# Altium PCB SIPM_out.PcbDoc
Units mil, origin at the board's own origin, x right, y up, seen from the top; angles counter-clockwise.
Board outline 1885 x 1885 mil, 2 copper layers (Top Layer, Bottom Layer); 43 components, 15 nets, 149 pads, 10 vias.
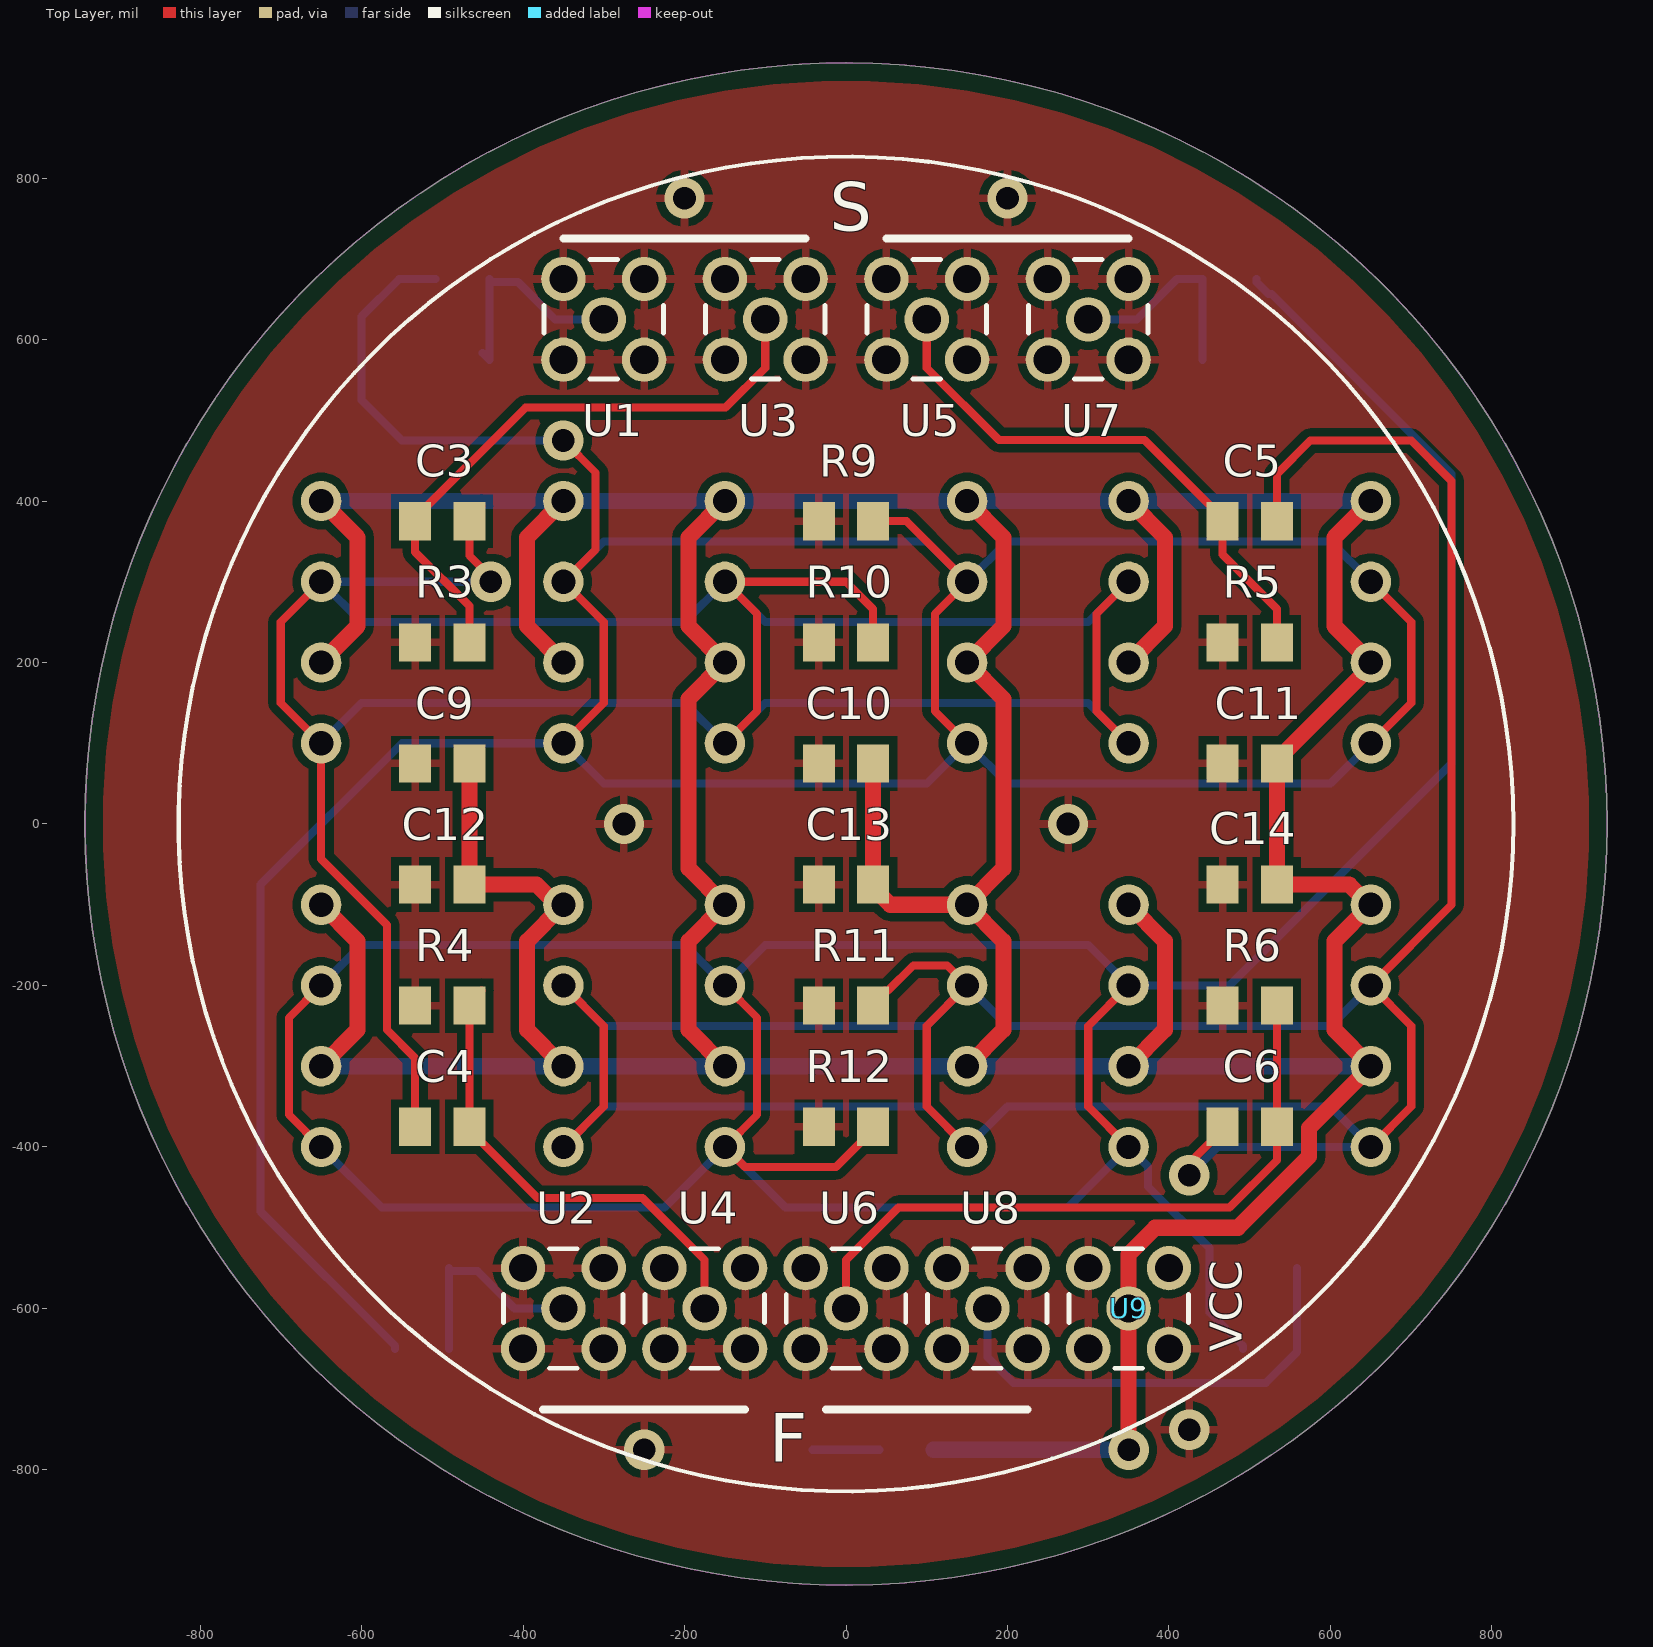
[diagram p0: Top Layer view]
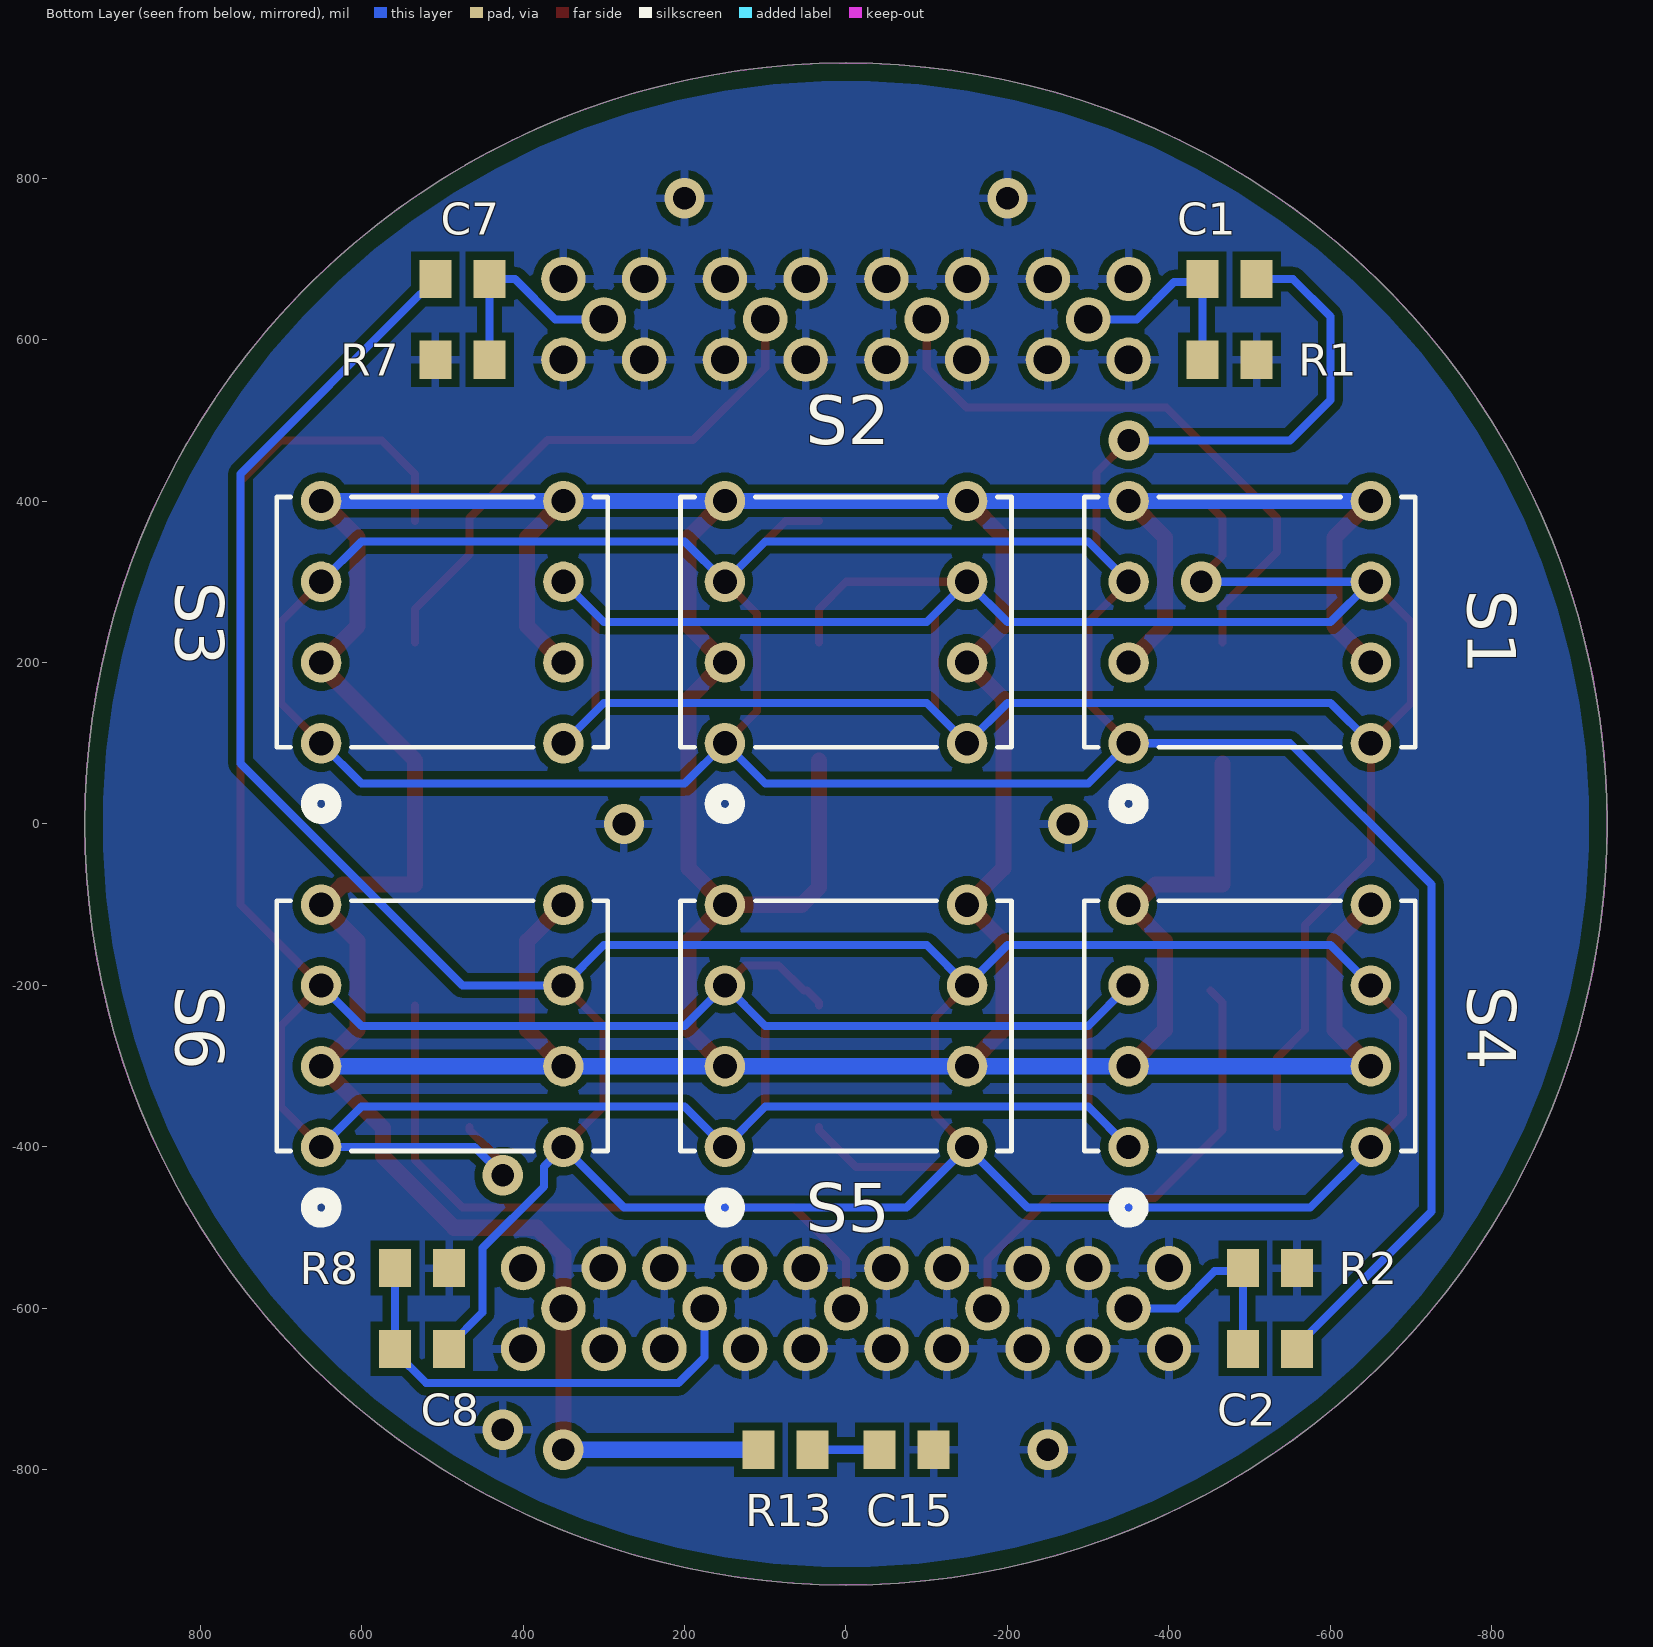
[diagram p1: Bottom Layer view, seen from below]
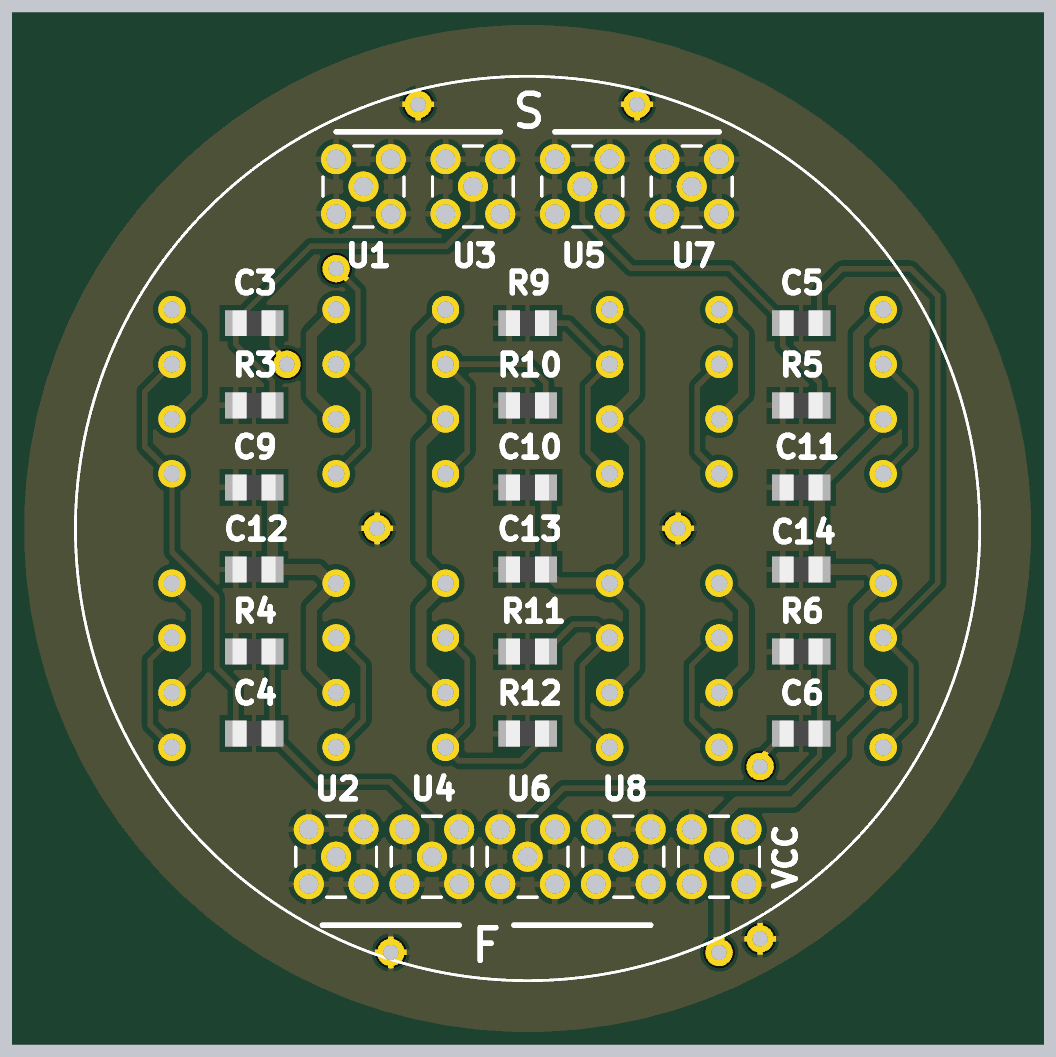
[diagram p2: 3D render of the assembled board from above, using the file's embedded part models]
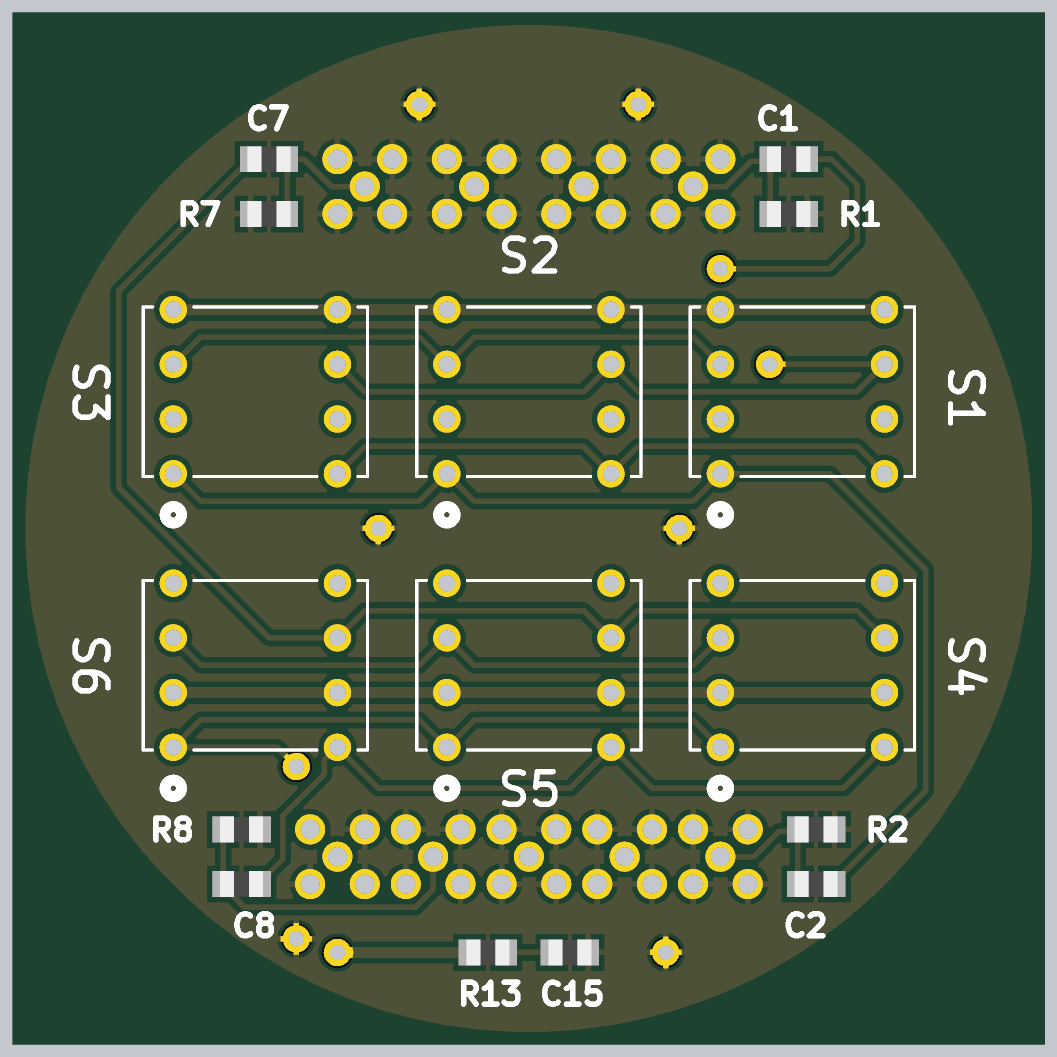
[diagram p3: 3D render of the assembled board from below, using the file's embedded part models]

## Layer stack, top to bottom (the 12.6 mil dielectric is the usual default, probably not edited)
Top Solder: solder mask 0.4, Solder Resist, Dk 3.5
Top Layer: signal copper 1.4
Dielectric 1: dielectric 12.6, FR-4, Dk 4.8
Bottom Layer: signal copper 1.4
Bottom Solder: solder mask 0.4, Solder Resist, Dk 3.5

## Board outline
0,-942.5 cw(c0,0) -942.5,0 cw(c0,0) 0,942.5 cw(c0,0) 942.5,0 cw(c0,0)

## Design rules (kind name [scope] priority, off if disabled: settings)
Clearance [All] p1: gap=10 ignorepadtopadclearanceinfootprint=FALSE except(0: Arc-Hole Track-Hole SMDPad-Hole THPad-Hole Via-Hole Fill-Hole Poly-Hole Region-Hole Text-Hole)
PolygonConnect [All] p1: connectstyle=Relief reliefconductorwidth=10 reliefentries=4 polygonreliefangle="90 Angle" airgapwidth=10
RoutingVias [All] p1: holewidth=28 width=50 viastyle="Through Hole" minholewidth=28 minwidth=50 maxholewidth=28 maxwidth=50
SolderMaskExpansion [All] p1: expansion=4 istentingtop=FALSE
Width vcc [InNet('VCC')] p1: maxlimit=20 minlimit=20 preferedwidth=20 minimp=50.000000 maximp=50.000000 favimp=50.000000
Width default [All] p2: maxlimit=10 minlimit=10 preferedwidth=10
30 further rules are at their usual default settings.

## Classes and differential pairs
component class Power: C9 C10 C11 C12 C13 C14 C15 R13
component class Output: C1 C2 C3 C4 C5 C6 C7 C8 R2 R3 R4 R5 R6 R7 R8 R9 R10 R11 R12 S1 S2 S3 S4 S5 S6 U1 U2 U3 U4 U5 U6 U7 U8

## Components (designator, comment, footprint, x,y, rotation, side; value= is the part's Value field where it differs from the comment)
C1 "100nF" 0805 -475,675 r180 bottom
C2 "390pF" 0805 -525,-650 r0 bottom
C3 "100nF" 0805 -500,375 r0 top
C4 "390pF" 0805 -500,-375 r0 top
C5 "100nF" 0805 500,375 r0 top
C6 "390pF" 0805 500,-375 r0 top
C7 "100nF" 0805 475,675 r0 bottom
C8 "390pF" 0805 525,-650 r0 bottom
C9 "10nF" 0805 -500,75 r0 top
C10 "10nF" 0805 0,75 r0 top
C11 "10nF" 0805 500,75 r0 top
C12 "10nF" 0805 -500,-75 r0 top
C13 "10nF" 0805 0,-75 r0 top
C14 "10nF" 0805 500,-75 r0 top
C15 "1uF" 0805 -75,-775 r0 bottom
R1 "51R" 0805 -475,575 r0 bottom
R2 "51R" 0805 -525,-550 r0 bottom
R3 "51R" 0805 -500,225 r0 top
R4 "51R" 0805 -500,-225 r0 top
R5 "51R" 0805 500,225 r0 top
R6 "51R" 0805 500,-225 r0 top
R7 "51R" 0805 475,575 r180 bottom
R8 "51R" 0805 525,-550 r0 bottom
R9 "1k" 0805 0,375 r0 top
R10 "1k" 0805 0,225 r0 top
R11 "1k" 0805 0,-225 r0 top
R12 "1k" 0805 0,-375 r0 top
R13 "100R" 0805 75,-775 r180 bottom
S1 "110-87-308-41-001101" "DIP 2x4" -350,100 r90 bottom
S2 "110-87-308-41-001101" "DIP 2x4" 150,100 r90 bottom
S3 "110-87-308-41-001101" "DIP 2x4" 650,100 r90 bottom
S4 "110-87-308-41-001101" "DIP 2x4" -350,-400 r90 bottom
S5 "110-87-308-41-001101" "DIP 2x4" 150,-400 r90 bottom
S6 "110-87-308-41-001101" "DIP 2x4" 650,-400 r90 bottom
U1 "MMCX Jack" MMCX -300,625 r90 top
U2 "MMCX Jack" MMCX -350,-600 r90 top
U3 "MMCX Jack" MMCX -100,625 r90 top
U4 "MMCX Jack" MMCX -175,-600 r90 top
U5 "MMCX Jack" MMCX 100,625 r90 top
U6 "MMCX Jack" MMCX 0,-600 r90 top
U7 "MMCX Jack" MMCX 300,625 r90 top
U8 "MMCX Jack" MMCX 175,-600 r90 top
U9 "MMCX Jack" MMCX 350,-600 r90 top

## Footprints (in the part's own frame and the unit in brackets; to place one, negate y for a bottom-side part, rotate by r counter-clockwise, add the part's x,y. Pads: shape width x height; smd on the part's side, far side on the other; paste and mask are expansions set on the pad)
0805 [mm]
  rect 1.006x1.2 smd paste+0 mask+0: 1(-0.853,0) 2(0.853,0)
  body extent -1,-0.6 1,0.6, height 0.71
"DIP 2x4" [mil] "808-AG11D"
  round 50 hole 30 mask+0: 1(0,0) 2(100,0) 3(200,0) 4(300,0) 5(0,-300) 6(100,-300) 7(200,-300) 8(300,-300)
  silkscreen extent -90,-355 305,55, body extent 0,0 10,10, height 10
MMCX [mil]
  round 55 hole 35 mask+0: 1(0,0) 2(-50,50) 3(50,50) 4(-50,-50) 5(50,-50)
  silkscreen extent -74,-74 74,74, body extent 0,0 10,10, height 10

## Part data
C1 C3 C5 C7: "CAP CER 0.1UF 50V X7R 0805", Case Code (Imperial)=0805, Case Code (Metric)=2012, Dielectric=X7R, Dielectric Material=Ceramic, Insulation Resistance=100GR, Manufacturer="Kyocera AVX", Manufacturer Part Number=08055C104JAT2A, Max Operating Temperature=125°C, Min Operating Temperature=-55°C, Package Quantity=1, Tolerance=5%, Voltage=50V
C2 C4 C6 C8: "CAP CER 390PF 50V C0G/NP0 0805", Case Code (Imperial)=0805, Case Code (Metric)=2012, Dielectric=C0G, Dielectric Material=Ceramic, Manufacturer="Kyocera AVX", Manufacturer Part Number=08055A391JAT2A, Max Operating Temperature=125°C, Min Operating Temperature=-55°C, Package Quantity=1, Temperature Coefficient=30ppm/°C, Tolerance=5%, Voltage=50V
C9 C10 C11 C12 C13 C14: "CAP CER 10000PF 50V X7R 0805", Case Code (Imperial)=0805, Case Code (Metric)=2012, Dielectric=X7R, Dielectric Material=Ceramic, Insulation Resistance=100GR, Manufacturer="Kyocera AVX", Manufacturer Part Number=08055C103KAT2A, Max Operating Temperature=125°C, Min Operating Temperature=-55°C, Package Quantity=1, Tolerance=10%, Voltage=50V
C15: "CAP CER 1UF 50V X7R 0805", Case Code (Imperial)=0805, Case Code (Metric)=2012, Dielectric=X7R, Manufacturer="Kyocera AVX", Manufacturer Part Number=08055C105KAT2A, Max Operating Temperature=125°C, Min Operating Temperature=-55°C, Package Quantity=1, Tolerance=10%, Voltage=50V
R1 R2 R3 R4 R5 R6 R7 R8: "RES SMD 51 OHM 5% 1/2W 0805", Case Code (Imperial)=0805, Case Code (Metric)=2012, Manufacturer=Panasonic, Manufacturer Part Number=ERJ-P06J510V, Max Operating Temperature=155°C, Max Power Dissipation=500mW, Min Operating Temperature=-55°C, Package Quantity=1, Resistor Type="Thick Film", Temperature Coefficient=200ppm/°C, Tolerance=5%, Voltage Rating=150V
R9 R10 R11 R12: "RES SMD 1K OHM 0.1% 1W 0805", Case Code (Imperial)=0805, Case Code (Metric)=2012, Manufacturer="Vishay Dale Thin Film", Manufacturer Part Number=PCAN0805E1001BST5, Max Operating Temperature=155°C, Max Power Dissipation=1W, Min Operating Temperature=-55°C, Resistance=1kR, Resistor Type="Thin Film", Temperature Coefficient=25ppm/°C, Tolerance=0.1%
R13: "RES SMD 100 OHM 1% 1/2W 0805", Case Code (Imperial)=0805, Case Code (Metric)=2012, Manufacturer=Panasonic, Manufacturer Part Number=ERJ-P06F1000V, Max Operating Temperature=155°C, Min Operating Temperature=-55°C, Package Quantity=5000, Power Rating=500mW, Resistor Type="Thick Film", Temperature Coefficient=100ppm/°C, Tolerance=1%, Voltage Rating=150V
S1 S2 S3 S4 S5 S6: "CONN IC DIP SOCKET 8POS GOLD", Contact Resistance=10mR, Current Rating=1A, Insulation Resistance=10GR, Manufacturer=Preci-Dip, Max Operating Temperature=125°C, Min Operating Temperature=-55°C, Package Quantity=52, Supplier Part Number 1=1212-1003-ND, Voltage Rating=150V, Voltage Rating (AC)=100V
U1 U2 U3 U4 U5 U6 U7 U8 U9: "CONN MMCX PLUG STR 50 OHM PCB", Frequency=6Hz, Manufacturer=Samtec, Manufacturer Part Number=MMCX-P-P-H-ST-TH1, Max Frequency=6GHz, Max Operating Temperature=90°C, Min Operating Temperature=-40°C, Operating Frequency="0 to 6Hz", Supplier Part Number 1=SAM10618-ND

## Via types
v1: diameter 50, hole 28, Top Layer to Bottom Layer, 10 vias

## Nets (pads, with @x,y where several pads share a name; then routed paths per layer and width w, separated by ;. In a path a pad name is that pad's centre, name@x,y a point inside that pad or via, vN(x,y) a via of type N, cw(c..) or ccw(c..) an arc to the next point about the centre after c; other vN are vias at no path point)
GND: C9.1 C10.1 C11.1 C12.1 C13.1 C14.1 C15.1 R1.1 R2.1 R3.1 R4.1 R5.1 R6.1 R7.1 R8.1 R9.1 R10.1 R11.1 R12.1 U1.2 U1.3 U1.4 U1.5 U2.2 U2.3 U2.4 U2.5 U3.2 U3.3 U3.4 U3.5 U4.2 U4.3 U4.4 U4.5 U5.2 U5.3 U5.4 U5.5 U6.2 U6.3 U6.4 U6.5 U7.2 U7.3 U7.4 U7.5 U8.2 U8.3 U8.4 U8.5 U9.2 U9.3 U9.4
  other v1: -250,-775 425,-750 -275,0 275,0 -200,775 200,775
NetC1_1: C1.1 R1.2 U1.1 | length 272.7
  Bottom Layer w10: R1.2@-450,583.57 R1.2 C1.1@-441.43,671.17 ; C1.1 C1.1@-441.43,671.17 ; U1.1 -360.1,625 -406.28,671.17 C1.1@-441.43,671.17
NetC1_2: C1.2 C2.1 R9.2 S1.1 S1.3 S2.1 S2.3 S3.1 S3.3 | length 4813.5
  Top Layer w10: S1.1 -300,150 -300,250 S1.3 -310,340 -310,435 v1(-350,475) ; R9.2 75,375 S2.3 110,260 110,140 S2.1 ; S3.1 700,150 700,250 S3.3
  Bottom Layer w10: C2.1 -558.57,-646.17 -725,-479.75 -725,-75 -550,100 S1.1 -300,50 100,50 S2.1 200,50 600,50 S3.1 ; C1.2 -553.37,675 -600,628.37 -600,525 -550,475 v1(-350,475) ; S1.3 -300,350 100,350 S2.3 200,350 600,350 S3.3
NetC2_2: C2.2 R2.2 U2.1 | length 260.6
  Bottom Layer w10: C2.2 R2.2 ; R2.2@-491.43,-553.83 -456.59,-553.83 -439.17,-571.25 -439.1,-571.25 -438.46,-571.89 -437.47,-572.89 -437.47,-573.05 -410.52,-600 U2.1
NetC3_1: C3.1 R3.2 U3.1 | length 752.4
  Top Layer w10: R3.2 -466.43,269.86 -533.57,337.01 -533.57,378.83 -396.69,515.71 -149.18,515.71 -100,564.9 U3.1
NetC3_2: C3.2 C4.1 R10.2 S1.5 S1.7 S2.5 S2.7 S3.5 S3.7 | length 3956.2
  Top Layer w10: S1.7 -700,250 -700,150 S1.5 -650,-43.43 -568.37,-125.06 -568.37,-254.84 -533.57,-289.63 C4.1 ; C3.2@-451.63,393.62 -466.43,378.83 C3.2 -466.43,332.31 -440,305.88 v1(-440,300) ; S2.5 -110,140 -110,260 S2.7 0,300 33.57,266.43 R10.2 ; S3.5 310,140 310,260 S3.7
  Bottom Layer w10: S1.5 -600,150 -200,150 S2.5 -100,150 300,150 S3.5 ; v1(-440,300) S1.7 -600,250 -200,250 S2.7 -100,250 300,250 S3.7
NetC4_2: C4.2 R4.2 U4.1 | length 596.8
  Top Layer w10: R4.2@-451.63,-206.38 -466.43,-221.17 R4.2 C4.2 -466.43,-378.83 -382.24,-463.01 -251.89,-463.01 -175,-539.9 U4.1
NetC5_1: C5.1 R5.2 U5.1 | length 685.2
  Top Layer w10: U5.1 100,564.9 189.39,475.51 369.74,475.51 466.43,378.83 C5.1 466.43,333.57 533.57,266.43 R5.2
NetC5_2: C5.2 C6.1 R11.2 S4.1 S4.3 S5.1 S5.3 S6.1 S6.3 | length 4335.6
  Top Layer w10: S4.1 -300,-350 -300,-250 S4.3 ; R11.2 33.57,-221.17 48.37,-206.38 52.2,-206.38 83.57,-175 125,-175 S5.3 100,-250 100,-350 S5.1 ; v1(425,-435) 432.65,-427.35 432.65,-412.6 466.43,-378.83 C6.1 ; C5.2 533.57,433.57 575,475 700,475 750,425 750,-100 S6.3 700,-250 700,-350 S6.1
  Bottom Layer w10: S4.1 -300,-350 100,-350 S5.1 200,-350 600,-350 S6.1 460,-400 v1(425,-435) ; S4.3 -300,-250 100,-250 S5.3 200,-250 600,-250 S6.3
NetC6_2: C6.2 R6.2 U6.1 | length 836.2
  Top Layer w10: U6.1 0,-539.9 64.9,-475 475,-475 533.57,-416.43 R6.2
NetC7_1: C7.1 R7.2 U7.1 | length 262.1
  Bottom Layer w10: U7.1 360.1,625 410.1,675 C7.1 R7.2
NetC7_2: C7.2 C8.1 R12.2 S4.5 S4.7 S5.5 S5.7 S6.5 S6.7 | length 4656.4
  Top Layer w10: S4.5 -690,-360 -690,-240 S4.7 ; S5.7 -110,-240 -110,-360 S5.5 -125,-425 -12.6,-425 33.57,-378.83 R12.2 ; S6.5 300,-350 300,-250 S6.7
  Bottom Layer w10: S4.5 -575,-475 -225,-475 S5.5 -75,-475 275,-475 S6.5 374.19,-424.19 374.19,-449.19 450,-525 450,-604.75 491.43,-646.17 C8.1 ; S4.7 -600,-150 -200,-150 S5.7 -100,-150 300,-150 S6.7 475,-200 750,75 750,433.57 527.2,656.38 523.37,656.38 508.57,671.17 C7.2
NetC8_2: C8.2 R8.2 U8.1 | length 576.9
  Bottom Layer w10: U8.1 175,-660.1 207.4,-692.5 519.9,-692.5 558.57,-653.83 C8.2 R8.2
NetC15_2: C15.2 R13.2 | length 82.9
  Bottom Layer w10: C15.2 R13.2
VCC: C9.2 C10.2 C11.2 C12.2 C13.2 C14.2 R13.1 S1.2 S1.4 S1.6 S1.8 S2.2 S2.4 S2.6 S2.8 S3.2 S3.4 S3.6 S3.8 S4.2 S4.4 S4.6 S4.8 S5.2 S5.4 S5.6 S5.8 S6.2 S6.4 S6.6 S6.8 U9.1 | length 8032.3
  Top Layer w20: S4.6 -605,-255 -605,-145 S4.8 ; S1.6 -605,245 -605,355 S1.8 ; C9.2 C12.2 -383.12,-75 -358.12,-100 S4.4 -395,-145 -395,-255 S4.2 ; S1.2 -395,245 -395,355 S1.4 ; S5.6 -195,-255 -195,-145 S5.8 -195,-55 -195,155 S2.6 -195,245 -195,355 S2.8 ; C10.2@33.57,78.83 C10.2 C13.2 33.57,-78.83 54.75,-100 S5.4 ; S5.2 195,-255 195,-145 S5.4 ; S2.4 195,355 195,245 S2.2 195,155 195,-55 S5.4 ; v1(350,-775) U9.1 350,-532.82 382.82,-500 485.36,-500 573.37,-411.99 573.37,-376.63 S6.2 605,-255 605,-145 S6.4 648.28,-100 623.28,-75 C14.2 C11.2 533.57,78.83 650,195.25 S3.2 605,245 605,355 S3.4 ; S6.6 395,-255 395,-145 S6.8 ; S3.6 395,245 395,355 S3.8
  Bottom Layer w20: S4.6 S4.2 S5.6 S5.2 S6.6 S6.2 ; S1.8 S1.4 S2.8 S2.4 S3.8 S3.4 ; R13.1 v1(350,-775)
pads on no net: U9.5

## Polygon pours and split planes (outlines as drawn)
GND on Top Layer "GND_L01_P000" (solid, pour order 0): 0,-920 cw(c0,0) -920,0 cw(c0,0) 0,920 cw(c0,0) 920,0 cw(c0,0)
GND on Bottom Layer "GND_L02_P001" (solid, pour order 1): 0,-920 cw(c0,0) -920,0 cw(c0,0) 0,920 cw(c0,0) 920,0 cw(c0,0)

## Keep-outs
Keep-Out Layer:
  circle w1: c0,0 r942.5

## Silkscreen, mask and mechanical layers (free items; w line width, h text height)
Top Overlay:
  circle w5: c0,0 r826.5
  lines w10: -375,-725 -125,-725 ; -350,725 -50,725 ; -25,-725 225,-725 ; 50,725 350,725
  text "S" at -19.99,735 h60
  text "VCC" at 490,-653.32 h40 r90
  text "F" at -94.99,-790 h60
Outline:
  circle w1: c0,0 r942.5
